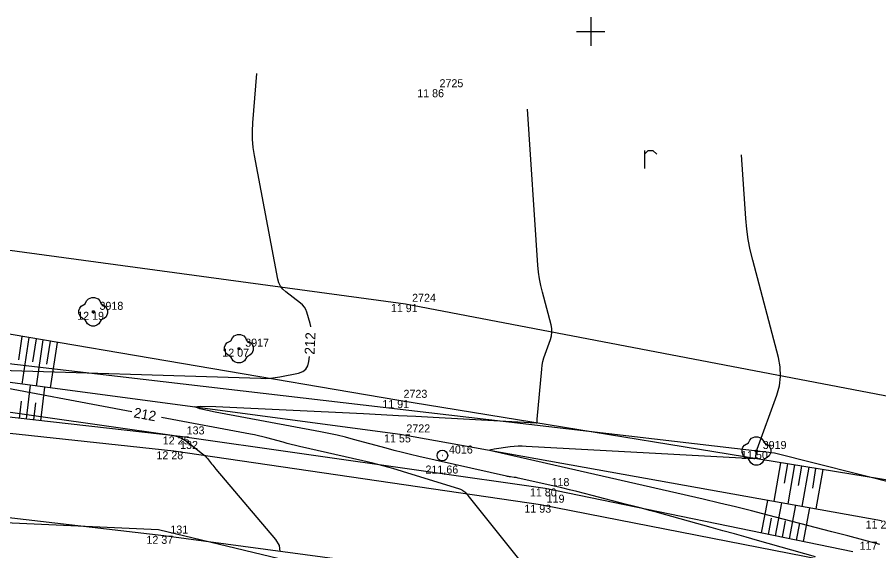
# Model space of a CAD drawing. Extents: x -703403 to -701924, y -1022520 to -1021856.
# Drawn here: x -702170.07 to -702139.92, y -1022268.17 to -1022249.5 of the extents above; entities that cross this region are included whole.
import ezdxf

# ---------------------------------------------------------------- set-up
doc = ezdxf.new("R2010")
doc.units = 0
for name, color, linetype in [('Ex_Contour Labels', 7, 'Continuous'), ('Ex_Major Contours', 7, 'Continuous'), ('Ex_Minor Contours', 7, 'Continuous'), ('Z_bodove_pole', 7, 'Continuous'), ('Z_bodove_pole_cisla', 7, 'Continuous'), ('Z_bodove_pole_vysky', 7, 'Continuous'), ('Z_body', 7, 'Continuous'), ('Z_body_cisla', 7, 'Continuous'), ('Z_body_vysky_redukovane', 7, 'Continuous'), ('Z_hektometricka_sit', 7, 'Continuous'), ('Z_hrany_paty', 7, 'Continuous'), ('Z_katastr_hranice', 7, 'Continuous'), ('Z_komunikace', 7, 'Continuous'), ('Z_komunikace_osa', 7, 'Continuous'), ('Z_pole_rozhranni', 7, 'Continuous'), ('Z_technicke_srafy', 7, 'Continuous'), ('Z_zelen_jednotliva', 7, 'Continuous'), ('Z_znaky_kultur', 7, 'Continuous')]:
    doc.layers.add(name, color=color, linetype=linetype)

# ---------------------------------------------------------------- blocks, each defined once
blk = doc.blocks.new('POINT_DISPLAY')
blk.add_line((0, 0), (0, 0))
blk = doc.blocks.new('Z24')
for p, q in [((-0.28, 0.28), (-0.23, 0.38)), ((-0.23, 0.38), (-0.17, 0.45)), ((-0.17, 0.45), (-0.05, 0.5)), ((-0.05, 0.5), (0.05, 0.5)), ((0.05, 0.5), (0.17, 0.45)), ((0.17, 0.45), (0.23, 0.38)), ((0.23, 0.38), (0.28, 0.28)), ((-0.5, 0.05), (-0.47, 0.13)), ((-0.5, -0.05), (-0.5, 0.05)), ((-0.47, 0.13), (-0.42, 0.2)), ((-0.42, 0.2), (-0.28, 0.28)), ((-0.03, -0.03), (-0.03, 0.03)), ((-0.03, 0.03), (0.03, 0.03)), ((0.03, 0.03), (0.03, -0.03)), ((0.28, 0.28), (0.42, 0.2)), ((0.42, 0.2), (0.47, 0.13)), ((0.47, 0.13), (0.5, 0.05)), ((0.5, 0.05), (0.5, -0.05)), ((-0.45, -0.17), (-0.5, -0.05)), ((-0.38, -0.23), (-0.45, -0.17)), ((-0.28, -0.28), (-0.38, -0.23)), ((-0.2, -0.42), (-0.28, -0.28)), ((0.03, -0.03), (-0.03, -0.03)), ((0.28, -0.28), (0.2, -0.42)), ((0.38, -0.23), (0.28, -0.28)), ((0.45, -0.17), (0.38, -0.23)), ((0.5, -0.05), (0.45, -0.17)), ((-0.13, -0.47), (-0.2, -0.42)), ((-0.05, -0.5), (-0.13, -0.47)), ((0.05, -0.5), (-0.05, -0.5)), ((0.13, -0.47), (0.05, -0.5)), ((0.2, -0.42), (0.13, -0.47))]:
    blk.add_line(p, q)
blk = doc.blocks.new('Z301')
for p, q in [((-0.13, 0.38), (-0.13, -0.25)), ((-0.13, 0.25), (0, 0.38)), ((0, 0.38), (0.17, 0.38)), ((0.17, 0.38), (0.3, 0.25))]:
    blk.add_line(p, q)
blk = doc.blocks.new('Z101')
for radius in [0.188, 0.0025]:
    blk.add_circle((0, 0), radius)

msp = doc.modelspace()

# ---------------------------------------------------------------- linework, layer by layer
at = {"layer": 'Ex_Major Contours'}
for points in [[(-702159.792, -1022260.33), (-702159.793, -1022260.319), (-702159.818, -1022260.22), (-702159.935, -1022259.824), (-702159.971, -1022259.73), (-702160.02, -1022259.645), (-702160.082, -1022259.569), (-702160.157, -1022259.502), (-702160.67, -1022259.114), (-702160.771, -1022259.021), (-702160.852, -1022258.916), (-702160.91, -1022258.797), (-702160.948, -1022258.664), (-702161.764, -1022254.34), (-702161.808, -1022254.055), (-702161.833, -1022253.77), (-702161.839, -1022253.483), (-702161.825, -1022253.195), (-702161.687, -1022251.467)], [(-702171.442, -1022261.833), (-702161.543, -1022262.137), (-702161.376, -1022262.138), (-702161.209, -1022262.129), (-702161.043, -1022262.11), (-702160.878, -1022262.083), (-702160.22, -1022261.953), (-702160.074, -1022261.903), (-702159.965, -1022261.82), (-702159.894, -1022261.704), (-702159.861, -1022261.553), (-702159.845, -1022261.379)], [(-702166.053, -1022263.314), (-702171.405, -1022262.311)], [(-702152.463, -1022268.509), (-702154.288, -1022266.233), (-702154.308, -1022266.21), (-702154.329, -1022266.189), (-702154.351, -1022266.168), (-702154.374, -1022266.149), (-702154.47, -1022266.074), (-702154.495, -1022266.057), (-702154.521, -1022266.042), (-702154.548, -1022266.029), (-702154.577, -1022266.019), (-702156.582, -1022265.395), (-702156.927, -1022265.292), (-702157.274, -1022265.195), (-702157.622, -1022265.105), (-702157.973, -1022265.022), (-702160.192, -1022264.519), (-702160.336, -1022264.486), (-702160.479, -1022264.451), (-702160.622, -1022264.415), (-702160.765, -1022264.377), (-702161.335, -1022264.222), (-702161.478, -1022264.185), (-702161.621, -1022264.151), (-702161.765, -1022264.119), (-702161.91, -1022264.091), (-702165.021, -1022263.508)]]:
    msp.add_lwpolyline(points, dxfattribs=at)
at = {"layer": 'Ex_Minor Contours'}
for points in [[(-702142.13, -1022268.388), (-702144.157, -1022267.814), (-702144.564, -1022267.699), (-702144.97, -1022267.585), (-702145.377, -1022267.472), (-702145.783, -1022267.359), (-702147.663, -1022266.839), (-702147.944, -1022266.762), (-702148.225, -1022266.686), (-702148.506, -1022266.611), (-702148.788, -1022266.537), (-702149.952, -1022266.234), (-702150.216, -1022266.166), (-702150.481, -1022266.101), (-702150.746, -1022266.037), (-702151.011, -1022265.975), (-702152.54, -1022265.627), (-702152.573, -1022265.62), (-702152.606, -1022265.614), (-702152.64, -1022265.608), (-702152.673, -1022265.604), (-702152.808, -1022265.587), (-702152.842, -1022265.583), (-702152.875, -1022265.578), (-702152.909, -1022265.571), (-702152.942, -1022265.564), (-702156.014, -1022264.868), (-702156.302, -1022264.802), (-702156.589, -1022264.732), (-702156.875, -1022264.659), (-702157.16, -1022264.583), (-702158.3, -1022264.274), (-702158.586, -1022264.2), (-702158.873, -1022264.131), (-702159.161, -1022264.068), (-702159.45, -1022264.011), (-702163.147, -1022263.318), (-702163.68, -1022263.206), (-702163.854, -1022263.136), (-702163.668, -1022263.108), (-702163.124, -1022263.122), (-702157.945, -1022263.374), (-702157.338, -1022263.404), (-702156.731, -1022263.435), (-702156.125, -1022263.467), (-702155.518, -1022263.5), (-702151.905, -1022263.699), (-702151.894, -1022263.698), (-702151.885, -1022263.693), (-702151.879, -1022263.685), (-702151.877, -1022263.674), (-702151.872, -1022263.608), (-702151.87, -1022263.581), (-702151.868, -1022263.568), (-702151.712, -1022261.815), (-702151.696, -1022261.682), (-702151.671, -1022261.55), (-702151.637, -1022261.42), (-702151.595, -1022261.292), (-702151.41, -1022260.783), (-702151.374, -1022260.655), (-702151.358, -1022260.527), (-702151.362, -1022260.397), (-702151.387, -1022260.267), (-702151.689, -1022259.127), (-702151.746, -1022258.893), (-702151.79, -1022258.656), (-702151.824, -1022258.418), (-702151.846, -1022258.178), (-702152.214, -1022252.721)], [(-702139.885, -1022267.959), (-702140.443, -1022267.804), (-702141.003, -1022267.653), (-702141.563, -1022267.506), (-702143.806, -1022266.922), (-702144.367, -1022266.778), (-702144.93, -1022266.638), (-702145.493, -1022266.503), (-702146.058, -1022266.372), (-702153.385, -1022264.702), (-702153.488, -1022264.672), (-702153.522, -1022264.646), (-702153.486, -1022264.623), (-702153.381, -1022264.603), (-702152.82, -1022264.529), (-702152.679, -1022264.514), (-702152.539, -1022264.506), (-702152.398, -1022264.504), (-702152.257, -1022264.508), (-702144.289, -1022264.946), (-702144.259, -1022264.944), (-702144.237, -1022264.932), (-702144.222, -1022264.912), (-702144.216, -1022264.883), (-702144.205, -1022264.748), (-702144.202, -1022264.714), (-702144.196, -1022264.681), (-702144.187, -1022264.648), (-702144.177, -1022264.616), (-702143.488, -1022262.725), (-702143.395, -1022262.398), (-702143.354, -1022262.069), (-702143.365, -1022261.737), (-702143.428, -1022261.403), (-702144.331, -1022258.004), (-702144.417, -1022257.643), (-702144.486, -1022257.279), (-702144.538, -1022256.912), (-702144.572, -1022256.543), (-702144.722, -1022254.316)], [(-702175.988, -1022262.515), (-702164.645, -1022264.131), (-702164.511, -1022264.159), (-702164.384, -1022264.203), (-702164.263, -1022264.263), (-702164.15, -1022264.34), (-702163.585, -1022264.777), (-702163.539, -1022264.815), (-702163.495, -1022264.855), (-702163.454, -1022264.898), (-702163.415, -1022264.944), (-702163.265, -1022265.131), (-702163.228, -1022265.177), (-702163.19, -1022265.224), (-702163.152, -1022265.27), (-702163.113, -1022265.316), (-702161.035, -1022267.779), (-702160.901, -1022267.994), (-702160.874, -1022268.194)]]:
    msp.add_lwpolyline(points, dxfattribs=at)
at = {"layer": 'Z_hektometricka_sit'}
for p, q in [((-702150, -1022249.5), (-702150, -1022250.5)), ((-702150.5, -1022250), (-702149.5, -1022250))]:
    msp.add_line(p, q, dxfattribs=at)
at = {"layer": 'Z_hrany_paty'}
for p, q in [((-702156.78, -1022262.9), (-702174.49, -1022259.89)), ((-702156.67, -1022264.1), (-702174.45, -1022261.74)), ((-702164.37, -1022264.17), (-702177.83, -1022262.65)), ((-702139.32, -1022265.75), (-702156.78, -1022262.9)), ((-702139.82, -1022267.12), (-702156.67, -1022264.1)), ((-702151.59, -1022265.99), (-702164.37, -1022264.17)), ((-702140.82, -1022268.21), (-702151.59, -1022265.99))]:
    msp.add_line(p, q, dxfattribs=at)
at = {"layer": 'Z_katastr_hranice'}
for p, q in [((-702143.57, -1022264.76), (-702188.97, -1022259.45)), ((-702287.01, -1022261.74), (-702165.12, -1022267.43)), ((-702114.48, -1022272.11), (-702143.57, -1022264.76)), ((-702165.12, -1022267.43), (-702081.55, -1022287.42))]:
    msp.add_line(p, q, dxfattribs=at)
at = {"layer": 'Z_komunikace'}
for p, q in [((-702164.59, -1022264.69), (-702177.9, -1022263.25)), ((-702151.76, -1022266.56), (-702164.59, -1022264.69)), ((-702140.85, -1022268.7), (-702151.76, -1022266.56))]:
    msp.add_line(p, q, dxfattribs=at)
at = {"layer": 'Z_komunikace_osa'}
for p, q in [((-702164.94, -1022267.65), (-702178.44, -1022266.08)), ((-702152.46, -1022269.32), (-702164.94, -1022267.65))]:
    msp.add_line(p, q, dxfattribs=at)
at = {"layer": 'Z_pole_rozhranni'}
for p, q in [((-702156.48, -1022259.54), (-702174.14, -1022257.15)), ((-702138.41, -1022263), (-702156.48, -1022259.54))]:
    msp.add_line(p, q, dxfattribs=at)
at = {"layer": 'Z_technicke_srafy'}
for p, q in [((-702169.91, -1022260.67), (-702170.03, -1022261.49)), ((-702169.66, -1022260.71), (-702169.91, -1022262.34)), ((-702169.41, -1022260.75), (-702169.54, -1022261.56)), ((-702169.17, -1022260.79), (-702169.41, -1022262.41)), ((-702168.92, -1022260.84), (-702169.04, -1022261.64)), ((-702168.67, -1022260.88), (-702168.92, -1022262.47)), ((-702169.74, -1022263.56), (-702169.6, -1022262.38)), ((-702169.24, -1022263.62), (-702169.1, -1022262.45)), ((-702169.99, -1022263.54), (-702169.92, -1022262.94)), ((-702169.49, -1022263.59), (-702169.42, -1022263)), ((-702143.36, -1022265.09), (-702143.59, -1022266.44)), ((-702143.11, -1022265.13), (-702143.23, -1022265.81)), ((-702142.87, -1022265.17), (-702143.1, -1022266.53)), ((-702142.62, -1022265.21), (-702142.74, -1022265.89)), ((-702142.37, -1022265.25), (-702142.61, -1022266.62)), ((-702142.13, -1022265.29), (-702142.24, -1022265.98)), ((-702141.88, -1022265.33), (-702142.12, -1022266.71)), ((-702144.02, -1022267.55), (-702143.8, -1022266.41)), ((-702143.53, -1022267.65), (-702143.31, -1022266.49)), ((-702143.04, -1022267.75), (-702142.82, -1022266.58)), ((-702142.55, -1022267.85), (-702142.33, -1022266.67)), ((-702143.78, -1022267.6), (-702143.67, -1022267.03)), ((-702143.29, -1022267.7), (-702143.18, -1022267.12)), ((-702142.8, -1022267.8), (-702142.68, -1022267.21))]:
    msp.add_line(p, q, dxfattribs=at)

# ---------------------------------------------------------------- block references
at = {"layer": 'Z_bodove_pole'}
msp.add_blockref('Z101', (-702155.19, -1022264.84), dxfattribs=at)
at = {"layer": 'Z_body'}
for p in [(-702155.51, -1022252.02), (-702156.48, -1022259.54), (-702167.41, -1022259.81), (-702162.31, -1022261.1), (-702156.78, -1022262.9), (-702156.67, -1022264.1), (-702164.37, -1022264.17), (-702164.59, -1022264.69), (-702144.2, -1022264.68), (-702155.19, -1022264.84), (-702151.59, -1022265.99), (-702151.76, -1022266.56), (-702164.94, -1022267.65)]:
    msp.add_blockref('POINT_DISPLAY', p, dxfattribs=at)
at = {"layer": 'Z_zelen_jednotliva'}
for p in [(-702167.41, -1022259.81), (-702162.31, -1022261.1), (-702144.2, -1022264.68)]:
    msp.add_blockref('Z24', p, dxfattribs=at)
at = {"layer": 'Z_znaky_kultur'}
msp.add_blockref('Z301', (-702147.99, -1022254.54), dxfattribs=at)

# ---------------------------------------------------------------- texts
at = {"layer": 'Ex_Contour Labels'}
for rotation, p in [(87.0772, (-702159.667, -1022261.315)), (349.383, (-702166.013, -1022263.5))]:
    msp.add_text('212', height=0.35, rotation=rotation, dxfattribs=at).set_placement(p)
at = {"layer": 'Z_bodove_pole_cisla'}
msp.add_text('4016', height=0.28, dxfattribs=at).set_placement((-702154.96, -1022264.77))
at = {"layer": 'Z_bodove_pole_vysky'}
msp.add_text('211,66', height=0.28, dxfattribs=at).set_placement((-702155.78, -1022265.47))
at = {"layer": 'Z_body_cisla'}
for s, p in [('2725', (-702155.29, -1022251.95)), ('2724', (-702156.25, -1022259.46)), ('3918', (-702167.19, -1022259.74)), ('3917', (-702162.09, -1022261.03)), ('2723', (-702156.55, -1022262.82)), ('133', (-702164.14, -1022264.1)), ('2722', (-702156.45, -1022264.03)), ('132', (-702164.37, -1022264.61)), ('3919', (-702143.98, -1022264.61)), ('118', (-702151.37, -1022265.91)), ('119', (-702151.54, -1022266.49)), ('131', (-702164.71, -1022267.57)), ('117', (-702140.59, -1022268.14))]:
    msp.add_text(s, height=0.28, dxfattribs=at).set_placement(p)
at = {"layer": 'Z_body_vysky_redukovane'}
for s, p in [('11 86', (-702156.07, -1022252.3)), ('11 91', (-702156.993, -1022259.82)), ('12 19', (-702167.97, -1022260.09)), ('12 07', (-702162.893, -1022261.38)), ('11 91', (-702157.293, -1022263.18)), ('12 25', (-702164.977, -1022264.45)), ('11 55', (-702157.23, -1022264.38)), ('12 28', (-702165.197, -1022264.97)), ('11 50', (-702144.737, -1022264.96)), ('11 80', (-702152.127, -1022266.27)), ('11 93', (-702152.32, -1022266.84)), ('11 27', (-702140.38, -1022267.4)), ('12 37', (-702165.547, -1022267.93))]:
    msp.add_text(s, height=0.28, dxfattribs=at).set_placement(p)

doc.saveas('drawing.dxf')
